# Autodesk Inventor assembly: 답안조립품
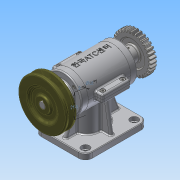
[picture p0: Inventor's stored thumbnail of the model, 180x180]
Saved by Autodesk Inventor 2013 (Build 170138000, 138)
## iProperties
Created: 2015-09
Part Number: 답안조립품
Document SubType Name: Assembly
Designer: Administrator
Mass: 2251.17 g
Surface Area: 1633.52 cm^2
Volume: 528.514 cm^3
Density: 4.25942 g/cm^3
Author: Administrator
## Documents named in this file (17)
- C:\Users\Administrator\Desktop\350908V1008\답안조립품.iam
- C:\Users\Administrator\Desktop\350908V1008\본체.ipt
- C:\Users\Administrator\Desktop\350908V1008\본체 커버.ipt
- C:\Users\Administrator\Desktop\350908V1008\M4x0.5x14.ipt
- C:\Users\Administrator\Desktop\350908V1008\뒤커버.ipt
- C:\Users\Administrator\Desktop\350908V1008\앞커버.ipt
- C:\Users\Administrator\Desktop\350908V1008\베어링 6201.ipt
- C:\Users\Administrator\Desktop\350908V1008\베어링 6202.ipt
- C:\Users\Administrator\Desktop\350908V1008\오일실.ipt
- C:\Users\Administrator\Desktop\350908V1008\M3x0.5x8.ipt
- C:\Users\Administrator\Desktop\350908V1008\편심축.ipt
- C:\Users\Administrator\Desktop\350908V1008\키4x4.ipt
- C:\Users\Administrator\Desktop\350908V1008\V-벨트풀리.ipt
- C:\Users\Administrator\Desktop\350908V1008\스퍼기어.ipt
- C:\Users\Administrator\Desktop\350908V1008\멈춤나사.ipt
- C:\Users\Administrator\Desktop\350908V1008\슬라이드.ipt
- C:\Users\Administrator\Desktop\350908V1008\가변스프링-1.ipt
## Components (14 placed, 4 different names)
1. M4x0.5x14:1
2. M4x0.5x14:2
3. M4x0.5x14:3
4. M4x0.5x14:4
5. V-벨트풀리:1 — 각도:3, 구동부
6. 가변스프링-1:1
7. M3x0.5x8:1
8. M3x0.5x8:3
9. M3x0.5x8:4
10. M3x0.5x8:5
11. M3x0.5x8:2
12. M3x0.5x8:6
13. M3x0.5x8:7
14. M3x0.5x8:8
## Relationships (2: Angle 2)
- 각도:3 [Angle]: V-벨트풀리:1
- 구동부 [Angle]: V-벨트풀리:1
